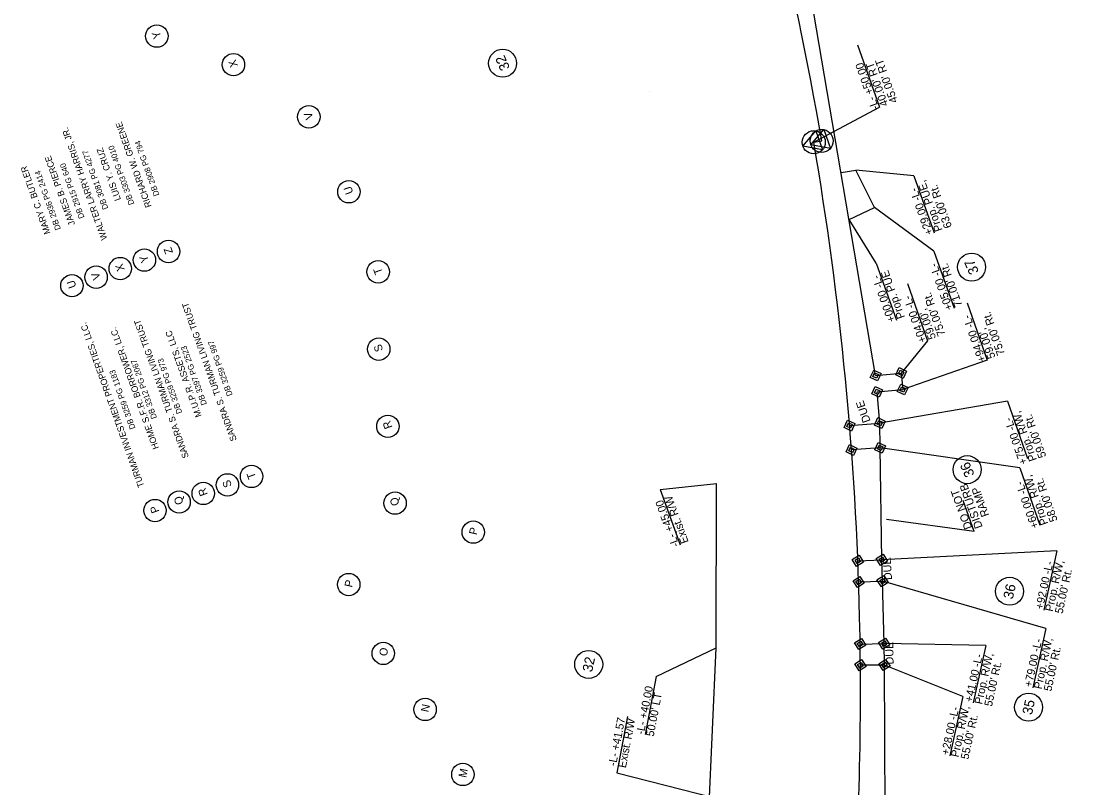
# Model space of a CAD drawing. Extents: x 1610947 to 1617684, y 899814 to 904658.
# Drawn here: x 1616215 to 1616872, y 902225 to 902704 of the extents above; entities that cross this region are included whole.
import ezdxf

# ---------------------------------------------------------------- set-up
doc = ezdxf.new("R2010")
doc.units = 0
for name, color, linetype in [('Prop Conc 1ft 6in Curb and Gutter', 7, 'Continuous'), ('Prop Dimension', 7, 'Continuous'), ('Prop EOT Dash', 7, 'Continuous'), ('Prop Hatching', 7, 'Continuous'), ('Prop Horizontal Alignment Curve and Spiral Data', 7, 'Continuous'), ('Prop Horizontal Alignment Direction Label', 7, 'Continuous'), ('Prop Horizontal Alignment Station Label', 7, 'Continuous'), ('Prop Horizontal Alignment Tick Label', 7, 'Continuous'), ('Prop Horizontal Alignment Tick Large', 7, 'Continuous'), ('Prop ROW Marker CELL', 7, 'Continuous'), ('Prop ROW RW Lines', 7, 'Continuous'), ('Prop ROW Station Offsets', 7, 'Continuous'), ('Scratch_Level_3', 7, 'Continuous')]:
    doc.layers.add(name, color=color, linetype=linetype)

msp = doc.modelspace()

# ---------------------------------------------------------------- linework, layer by layer
at = {"layer": 'Prop Conc 1ft 6in Curb and Gutter'}
for p, q in [((1616772.97, 902607.65), (1616785.65, 902571.92)), ((1616785.39, 902560.57), (1616798.07, 902524.84)), ((1616749.43, 902553.15), (1616762.12, 902517.42)), ((1616614.36, 902411.65), (1616649.55, 902415.33)), ((1616614.36, 902411.65), (1616627.03, 902376.95)), ((1616611.97, 902294.87), (1616649.42, 902312.76)), ((1616611.97, 902294.87), (1616604.97, 902258.6))]:
    msp.add_line(p, q, dxfattribs=at)
for points in [[(1616772.97, 902607.65), (1616736.63, 902611.12)], [(1616785.39, 902560.57), (1616748.32, 902587.82)], [(1616749.43, 902553.15), (1616732.47, 902580.28)]]:
    msp.add_lwpolyline(points, dxfattribs=at)
at = {"layer": 'Prop Dimension'}
for q in [(1616803.8, 902404.71), (1616755.87, 902392.89)]:
    msp.add_line((1616810.71, 902385.43), q, dxfattribs=at)
at = {"layer": 'Prop EOT Dash'}
for points in [[(1616745.67, 902481.66), (1616747.86, 902486.26), (1616752.45, 902484.07), (1616750.27, 902479.47)], [(1616761.6, 902483.2), (1616763.78, 902487.8), (1616768.38, 902485.61), (1616766.19, 902481.01)], [(1616763.29, 902483.8), (1616764.38, 902486.1), (1616766.68, 902485.01), (1616765.59, 902482.71)], [(1616747.37, 902482.26), (1616748.46, 902484.56), (1616750.76, 902483.47), (1616749.66, 902481.17)], [(1616746.63, 902471.41), (1616748.82, 902476.01), (1616753.42, 902473.82), (1616751.23, 902469.22)], [(1616748.33, 902472.01), (1616749.42, 902474.31), (1616751.72, 902473.22), (1616750.63, 902470.92)], [(1616762.57, 902472.87), (1616764.75, 902477.47), (1616769.35, 902475.28), (1616767.17, 902470.68)], [(1616764.26, 902473.47), (1616765.36, 902475.77), (1616767.66, 902474.68), (1616766.56, 902472.38)], [(1616729.39, 902450.37), (1616731.58, 902454.96), (1616736.17, 902452.78), (1616733.99, 902448.18)], [(1616731.09, 902450.97), (1616732.18, 902453.27), (1616734.48, 902452.18), (1616733.39, 902449.88)], [(1616748.33, 902451.92), (1616750.51, 902456.52), (1616755.11, 902454.33), (1616752.93, 902449.73)], [(1616750.02, 902452.52), (1616751.12, 902454.82), (1616753.41, 902453.73), (1616752.32, 902451.43)], [(1616730.58, 902435.11), (1616732.77, 902439.71), (1616737.37, 902437.52), (1616735.18, 902432.93)], [(1616748.54, 902436.45), (1616750.72, 902441.05), (1616755.32, 902438.86), (1616753.13, 902434.26)], [(1616732.28, 902435.72), (1616733.37, 902438.02), (1616735.67, 902436.92), (1616734.58, 902434.62)], [(1616750.23, 902437.05), (1616751.32, 902439.35), (1616753.62, 902438.26), (1616752.53, 902435.96)], [(1616734.44, 902367.84), (1616738.72, 902370.59), (1616741.47, 902366.31), (1616737.19, 902363.56)], [(1616736.2, 902367.46), (1616738.34, 902368.84), (1616739.71, 902366.69), (1616737.57, 902365.32)], [(1616749.43, 902368.45), (1616753.71, 902371.2), (1616756.46, 902366.91), (1616752.18, 902364.16)], [(1616751.18, 902368.07), (1616753.33, 902369.44), (1616754.7, 902367.3), (1616752.56, 902365.92)], [(1616734.93, 902354.59), (1616739.21, 902357.34), (1616741.96, 902353.06), (1616737.68, 902350.31)], [(1616736.69, 902354.21), (1616738.83, 902355.58), (1616740.21, 902353.44), (1616738.06, 902352.07)], [(1616749.92, 902355.1), (1616754.21, 902357.85), (1616756.96, 902353.57), (1616752.67, 902350.82)], [(1616751.68, 902354.72), (1616753.82, 902356.09), (1616755.2, 902353.95), (1616753.06, 902352.58)], [(1616735.88, 902315.85), (1616740.16, 902318.59), (1616742.91, 902314.31), (1616738.62, 902311.56)], [(1616737.63, 902315.46), (1616739.78, 902316.84), (1616741.15, 902314.69), (1616739.01, 902313.32)], [(1616750.87, 902316.07), (1616755.16, 902318.82), (1616757.91, 902314.53), (1616753.62, 902311.78)], [(1616752.63, 902315.69), (1616754.78, 902317.06), (1616756.15, 902314.92), (1616754.01, 902313.54)], [(1616736.03, 902302.59), (1616740.31, 902305.34), (1616743.06, 902301.05), (1616738.78, 902298.3)], [(1616737.79, 902302.2), (1616739.93, 902303.58), (1616741.3, 902301.43), (1616739.16, 902300.06)], [(1616751.03, 902302.71), (1616755.31, 902305.46), (1616758.06, 902301.18), (1616753.78, 902298.43)], [(1616752.79, 902302.33), (1616754.93, 902303.7), (1616756.3, 902301.56), (1616754.16, 902300.19)]]:
    msp.add_lwpolyline(points, close=True, dxfattribs=at)
at = {"layer": 'Prop Hatching'}
for centre in [(1616515.99, 902677.99), (1616809.01, 902550.59), (1616806.27, 902424.02), (1616832.74, 902348.04), (1616569.78, 902302.34), (1616844.63, 902275.59)]:
    msp.add_circle(centre, 8.75, dxfattribs=at)
at = {"layer": 'Prop Horizontal Alignment Curve and Spiral Data'}
for p, q in [((1616831.46, 902466.87), (1616751.72, 902453.13)), ((1616831.46, 902466.87), (1616843.99, 902431.08)), ((1616839.17, 902425.2), (1616751.93, 902437.66)), ((1616839.17, 902425.2), (1616851.7, 902389.41)), ((1616862.3, 902373.25), (1616854.22, 902336.21)), ((1616855.31, 902324.8), (1616847.22, 902287.75)), ((1616817.94, 902314.13), (1616810.11, 902278.26)), ((1616803.45, 902282.26), (1616795.37, 902245.21))]:
    msp.add_line(p, q, dxfattribs=at)
for points in [[(1616862.3, 902373.25), (1616752.94, 902367.68)], [(1616855.31, 902324.8), (1616753.44, 902354.33)], [(1616817.94, 902314.13), (1616754.39, 902315.3)], [(1616803.45, 902282.26), (1616754.55, 902301.94)]]:
    msp.add_lwpolyline(points, dxfattribs=at)
at = {"layer": 'Prop Horizontal Alignment Direction Label'}
for p, q in [((1616749.06, 902482.86), (1616674.19, 902922.42)), ((1616749.06, 902482.86), (1616764.99, 902484.4)), ((1616764.99, 902484.4), (1616765.96, 902474.07)), ((1616750.03, 902472.61), (1616765.96, 902474.07)), ((1616751.72, 902453.13), (1616750.03, 902472.61)), ((1616752.94, 902367.68), (1616751.93, 902437.66)), ((1616754.39, 902315.3), (1616753.44, 902354.33)), ((1616755.34, 902114.68), (1616754.55, 902301.94))]:
    msp.add_line(p, q, dxfattribs=at)
at = {"layer": 'Prop Horizontal Alignment Station Label'}
for centre in [(1616299.96, 902694.97), (1616347.83, 902677.11), (1616394.92, 902644.49), (1616419.94, 902597.7), (1616307.27, 902560.33), (1616292.18, 902555), (1616262.01, 902544.33), (1616277.1, 902549.66), (1616438.24, 902547.66), (1616246.93, 902539), (1616438.59, 902499.31), (1616444.32, 902451.09), (1616359.14, 902419.81), (1616344.05, 902414.48), (1616328.97, 902409.15), (1616313.88, 902403.81), (1616448.78, 902403.12), (1616298.8, 902398.48), (1616497.68, 902385), (1616419.83, 902352.21), (1616441.45, 902309.23), (1616467.57, 902274.19), (1616491.17, 902233.56)]:
    msp.add_circle(centre, 7, dxfattribs=at)
at = {"layer": 'Prop Horizontal Alignment Tick Label'}
for p, q in [((1616769.04, 902540.33), (1616781.57, 902504.54)), ((1616806.19, 902528.25), (1616818.72, 902492.46))]:
    msp.add_line(p, q, dxfattribs=at)
for points in [[(1616781.57, 902504.54), (1616764.99, 902484.4)], [(1616818.72, 902492.46), (1616765.96, 902474.07)]]:
    msp.add_lwpolyline(points, dxfattribs=at)
at = {"layer": 'Prop Horizontal Alignment Tick Large'}
for p, q in [((1616732.78, 902451.57), (1616751.72, 902453.13)), ((1616751.93, 902437.66), (1616751.72, 902453.13)), ((1616751.93, 902437.66), (1616733.98, 902436.32)), ((1616737.95, 902367.08), (1616752.94, 902367.68)), ((1616753.44, 902354.33), (1616752.94, 902367.68)), ((1616738.45, 902353.83), (1616753.44, 902354.33)), ((1616739.39, 902315.08), (1616754.39, 902315.3)), ((1616754.55, 902301.94), (1616754.39, 902315.3)), ((1616754.55, 902301.94), (1616739.55, 902301.82))]:
    msp.add_line(p, q, dxfattribs=at)
at = {"layer": 'Prop ROW Marker CELL'}
for p, q in [((1616710.42, 902628.61), (1616710.42, 902628.61)), ((1616715.35, 902629.45), (1616715.35, 902629.45)), ((1616749.06, 902482.86), (1616749.06, 902482.86)), ((1616764.99, 902484.4), (1616764.99, 902484.4)), ((1616750.03, 902472.61), (1616750.03, 902472.61)), ((1616765.96, 902474.07), (1616765.96, 902474.07)), ((1616751.72, 902453.13), (1616751.72, 902453.13)), ((1616732.78, 902451.57), (1616732.78, 902451.57)), ((1616733.98, 902436.32), (1616733.98, 902436.32)), ((1616751.93, 902437.66), (1616751.93, 902437.66)), ((1616752.94, 902367.68), (1616752.94, 902367.68)), ((1616737.95, 902367.08), (1616737.95, 902367.08)), ((1616753.44, 902354.33), (1616753.44, 902354.33)), ((1616738.45, 902353.83), (1616738.45, 902353.83)), ((1616739.39, 902315.08), (1616739.39, 902315.08)), ((1616754.39, 902315.3), (1616754.39, 902315.3)), ((1616739.55, 902301.82), (1616739.55, 902301.82)), ((1616754.55, 902301.94), (1616754.55, 902301.94))]:
    msp.add_line(p, q, dxfattribs=at)
for points in [[(1616720.84, 902624.77), (1616708.57, 902627.04), (1616716.65, 902636.55)], [(1616715.91, 902623.93), (1616703.64, 902626.2), (1616711.72, 902635.7)]]:
    msp.add_lwpolyline(points, close=True, dxfattribs=at)
for centre in [(1616715.35, 902629.45), (1616710.42, 902628.61)]:
    msp.add_circle(centre, 7.2, dxfattribs=at)
at = {"layer": 'Prop ROW RW Lines'}
msp.add_line((1616710.42, 902628.61), (1616715.35, 902629.45), dxfattribs=at)
for centre, radius, start, end in [((1614715.54, 902288.67), 2028.64, 9.67064, 18.33445), ((1614699.37, 902284.69), 2040.25, 1.32454, 9.70448), ((1614681.37, 902285.15), 2058.23, 355.7505, 1.30006)]:
    msp.add_arc(centre, radius, start, end, dxfattribs=at)
at = {"layer": 'Prop ROW Station Offsets'}
for p, q in [((1616737.68, 902689.45), (1616751.46, 902650.64)), ((1616710.42, 902628.61), (1616751.46, 902650.64)), ((1616594.06, 902269.68), (1616587.27, 902234.54)), ((1616587.27, 902234.54), (1616658.43, 902216.46))]:
    msp.add_line(p, q, dxfattribs=at)
at = {"layer": 'Scratch_Level_3'}
for p, q in [((1616607.99, 902660.42), (1616607.99, 902660.42)), ((1616727.47, 902609.65), (1616736.63, 902611.12)), ((1616748.32, 902587.82), (1616736.63, 902611.12)), ((1616732.47, 902580.28), (1616748.32, 902587.82)), ((1616649.42, 902312.76), (1616649.55, 902415.33)), ((1616642.43, 902157.05), (1616649.42, 902312.76))]:
    msp.add_line(p, q, dxfattribs=at)

# ---------------------------------------------------------------- texts
at = {"layer": 'Prop Conc 1ft 6in Curb and Gutter'}
for s, rotation, p in [('Prop. PUE,', 109.54863, (1616790.95, 902573.8)), ('+29.00 -L-', 109.54863, (1616785.06, 902571.71)), ("63.00' Rt.", 109.54863, (1616796.84, 902575.89)), ('+05.00 -L-', 109.54863, (1616797.48, 902524.63)), ("71.00' Rt.", 109.54863, (1616803.37, 902526.72)), ('+00.00 -L-', 109.54863, (1616761.53, 902517.21)), ('Prop. PUE', 109.54863, (1616767.42, 902519.3)), ('Exist. R/W', 110.05109, (1616632.31, 902378.88)), ('-L- +45.00', 110.05109, (1616626.44, 902376.74)), ('-L- +40.00', 79.07272, (1616604.22, 902258.18)), ("50.00' LT", 79.07272, (1616610.36, 902256.99))]:
    msp.add_text(s, height=5, rotation=rotation, dxfattribs=at).set_placement(p)
at = {"layer": 'Prop Dimension'}
for s, p in [('DISTURB', (1616815.99, 902388.24)), ('DO NOT', (1616809.44, 902387.73)), ('RAMP', (1616820.09, 902395.57))]:
    msp.add_text(s, height=5, rotation=109.83675, dxfattribs=at).set_placement(p)
at = {"layer": 'Prop Hatching'}
for s, rotation, p in [('32', 114.05949, (1616520.71, 902675.08)), ('37', 114.05949, (1616813.73, 902547.68)), ('36', 114.05949, (1616811.05, 902420.98)), ('36', 77.71667, (1616834.79, 902342.76)), ('32', 77.71667, (1616571.86, 902297.21)), ('35', 77.71667, (1616846.71, 902270.46))]:
    msp.add_text(s, height=6.25, rotation=rotation, dxfattribs=at).set_placement(p)
at = {"layer": 'Prop Horizontal Alignment Curve and Spiral Data'}
for s, rotation, p in [('Prop. R/W,', 109.30477, (1616849.89, 902430.25)), ('+75.00 -L-', 109.30477, (1616843.99, 902428.18)), ("59.00' Rt.", 109.30477, (1616855.78, 902432.31)), ('Prop. R/W,', 109.30477, (1616856.97, 902390.34)), ('+60.00 -L-', 109.30477, (1616851.07, 902388.27)), ("58.00' Rt.", 109.30477, (1616862.87, 902392.4)), ('+92.00 -L-', 77.68623, (1616853.61, 902336.34)), ('Prop. R/W,', 77.68623, (1616859.71, 902335.01)), ("55.00' Rt.", 77.68623, (1616865.82, 902333.67)), ('+79.00 -L-', 77.68623, (1616846.61, 902287.89)), ('Prop. R/W,', 77.68623, (1616852.72, 902286.55)), ('+41.00 -L-', 77.68623, (1616809.5, 902278.39)), ('Prop. R/W,', 77.68623, (1616815.6, 902277.06)), ("55.00' Rt.", 77.68623, (1616858.83, 902285.22)), ("55.00' Rt.", 77.68623, (1616821.71, 902275.73)), ('+28.00 -L-', 77.68623, (1616794.76, 902245.35)), ('Prop. R/W,', 77.68623, (1616800.86, 902244.02)), ("55.00' Rt.", 77.68623, (1616806.97, 902242.68))]:
    msp.add_text(s, height=5, rotation=rotation, dxfattribs=at).set_placement(p)
at = {"layer": 'Prop Horizontal Alignment Station Label'}
for s, height, rotation, p in [('Y', 5, 109.57069, (1616302.84, 902694.32)), ('X', 5, 109.57069, (1616350.72, 902676.47)), ('V', 5, 109.57069, (1616397.81, 902643.81)), ('WALTER LARRY HARRIS, JR.', 4, 109.57069, (1616269.07, 902568.32)), ('RICHARD W. GREENE', 4, 109.57069, (1616296.75, 902588.61)), ('LUIS Y. CRUZ', 4, 109.57069, (1616277.6, 902592.84)), ('DB 3303 PG 4010', 3.6, 109.57069, (1616285.94, 902590.17)), ('DB 2908 PG 794', 3.6, 109.57069, (1616301.62, 902595.68)), ('JAMES B. PIERCE', 4, 109.57069, (1616248.92, 902577.4)), ('DB 3081 PG 4277', 3.6, 109.57069, (1616269.7, 902587.32)), ('MARY C. BUTLER', 4, 109.57069, (1616233.54, 902571.91)), ('DB 2936 PG 2414', 3.6, 109.57069, (1616240.02, 902574.46)), ('DB 2915 PG 640', 3.6, 109.57069, (1616254.8, 902581.64)), ('U', 5, 109.57069, (1616422.82, 902597.05)), ('Z', 5, 109.57069, (1616310.14, 902559.72)), ('X', 5, 109.57069, (1616279.98, 902549.02)), ('Y', 5, 109.57069, (1616295.07, 902554.35)), ('V', 5, 109.57069, (1616264.91, 902543.65)), ('T', 5, 109.57069, (1616441.14, 902546.97)), ('U', 5, 109.57069, (1616249.81, 902538.35)), ('SANDRA S. TURMAN LIVING TRUST', 4, 109.57069, (1616349.96, 902442.64)), ('TURMAN INVESTMENT PROPERTIES, LLC.', 4, 109.57069, (1616292.17, 902413.7)), ('HOME S.F.R. BORROWER, LLC.', 4, 109.57069, (1616301.31, 902437.56)), ('SANDRA S. TURMAN LIVING TRUST', 4, 109.57069, (1616320.01, 902431.97)), ('M.U.P.R. ASSETS, LLC', 4, 109.57069, (1616328.03, 902457.59)), ('DB 3397 PG 2523', 3.6, 109.57069, (1616331.31, 902465.03)), ('DB 3259 PG 997', 3.6, 109.57069, (1616347.37, 902470.73)), ('S', 5, 109.57069, (1616441.46, 902498.7)), ('DB 3312 PG 2067', 3.6, 109.57069, (1616300.07, 902456.45)), ('DB 3259 PG 973', 3.6, 109.57069, (1616315.86, 902459.66)), ('DB 3259 PG 1183', 3.6, 109.57069, (1616286.66, 902449.98)), ('R', 5, 109.57069, (1616447.19, 902450.48)), ('T', 5, 109.57069, (1616362.03, 902419.13)), ('S', 5, 109.57069, (1616346.92, 902413.87)), ('Q', 5, 109.57069, (1616316.79, 902403.09)), ('R', 5, 109.57069, (1616331.84, 902408.54)), ('Q', 5, 109.57069, (1616451.69, 902402.4)), ('P', 5, 109.57069, (1616301.67, 902397.87)), ('P', 5, 77.19821, (1616499.77, 902382.95)), ('P', 5, 77.19821, (1616421.93, 902350.16)), ('O', 5, 77.19821, (1616443.53, 902307.11)), ('N', 5, 78.09451, (1616469.7, 902272.18)), ('M', 5, 78.09451, (1616493.24, 902231.23))]:
    msp.add_text(s, height=height, rotation=rotation, dxfattribs=at).set_placement(p)
at = {"layer": 'Prop Horizontal Alignment Tick Label'}
for s, p in [('+04.00 -L-', (1616780.98, 902504.34)), ("75.00' Rt.", (1616792.78, 902508.47)), ("59.00',", (1616786.88, 902506.4)), ('+94.00 -L-', (1616818.13, 902492.25)), ("75.00' Rt.", (1616829.93, 902496.39)), ("59.00',", (1616824.03, 902494.32))]:
    msp.add_text(s, height=5, rotation=109.30477, dxfattribs=at).set_placement(p)
at = {"layer": 'Prop Horizontal Alignment Tick Large'}
for rotation, p in [(109.30477, (1616745.98, 902454.38)), (93.8727, (1616759.35, 902355.2)), (90.93946, (1616760.29, 902302.36))]:
    msp.add_text('DUE', height=5, rotation=rotation, dxfattribs=at).set_placement(p)
at = {"layer": 'Prop ROW Station Offsets'}
for s, rotation, p in [('-L- +50.00', 109.54863, (1616751.18, 902649.93)), ("40.00' RT", 109.54863, (1616757.07, 902652.02)), ("45.00' RT", 109.54863, (1616762.96, 902654.12)), ('-L- +41.57', 79.07272, (1616586.85, 902238.5)), ('Exist. R/W', 79.07272, (1616592.98, 902237.31))]:
    msp.add_text(s, height=5, rotation=rotation, dxfattribs=at).set_placement(p)

doc.saveas('drawing.dxf')
